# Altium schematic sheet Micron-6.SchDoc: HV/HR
size A4; Date: 21.04.2016; Author: Andrey Bykanov; CompanyName: http://микрон.net; Engineer: Andrey Bykanov; Address1: HV/HR Вольтметр; Address2: (с) ООО "Микрон Сервис"; Address3: Тула, 2012-16г.; Address4: adm@микрон.net; Revision: 2.02; PageSetup: Record=PageOptions¦CenterHorizontal=False¦CenterVertical=False¦PrintScale=0.98¦XCorrection=1.00¦YCorrection=1.00¦PrintKind=1¦BorderSize=5000000¦LeftOffset=0¦BottomOffset=0¦Orientation=2¦PaperLength=1000¦PaperWidth=1000¦Scale=100¦PaperSource=7¦PrintQuality=-3¦MediaType=1¦DitherType=10¦PrintScaleMode=0¦PaperKind=A4¦PaperIndex=9
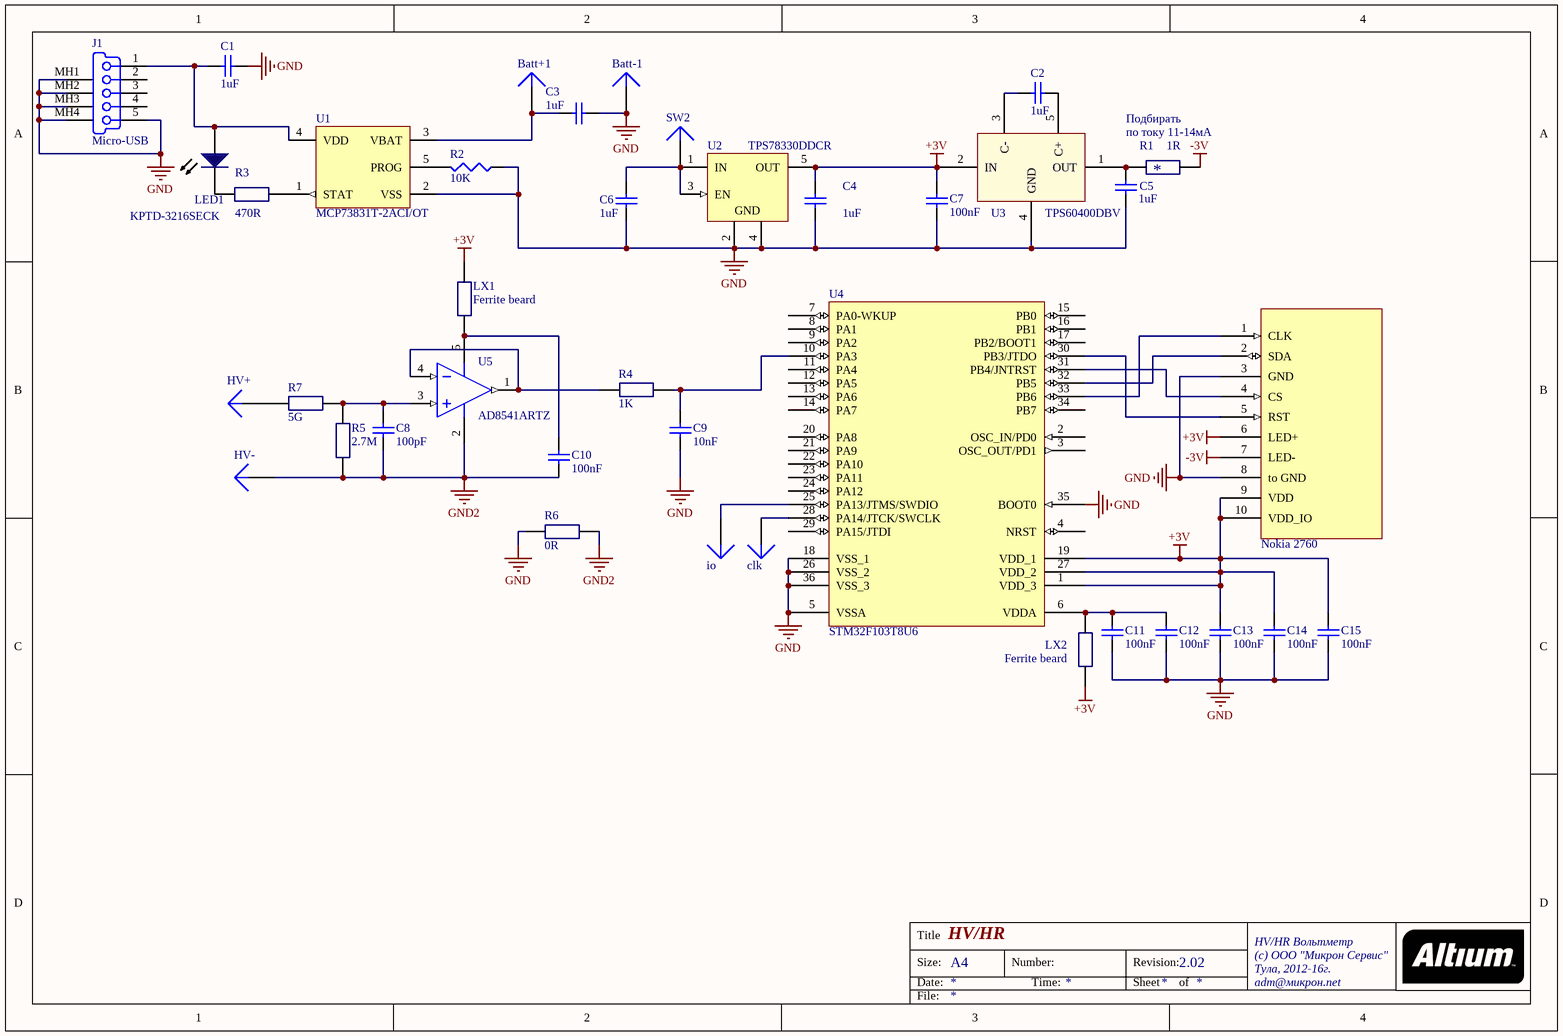
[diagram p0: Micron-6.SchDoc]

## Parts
Batt+1  (no value)  [Sensor contact]
Batt-1  (no value)  [Sensor contact]
C1  1uF  [0402 AVX]
C2  1uF  [0402 AVX]
C3  1uF  [0402 AVX]
C4  1uF  [1608[0603]]
C5  1uF  [0402 AVX]
C6  1uF  [1608[0603]]
C7  100nF  [0402 AVX]
C8  100pF  [0402 AVX]
C9  10nF  [0402 AVX]
C10  100nF  [0402 AVX]
C11  100nF  [0402 AVX]
C12  100nF  [0402 AVX]
C13  100nF  [0402 AVX]
C14  100nF  [0402 AVX]
C15  100nF  [0402 AVX]
clk  (no value)  [Sensor contact]
Display1  Nokia 2760  [DF23C-10DS-0.5V]
HV+  (no value)  [Sensor contact]
HV-  (no value)  [Sensor contact]
io  (no value)  [Sensor contact]
J1  Micro-USB  [47346-0001]
LED1  KPTD-3216SECK  [KPTD-3216SECK]
LX1  Ferrite beard  [Resistor]
LX2  Ferrite beard  [Resistor]
R1  1R  [1608[0603]]
R2  10K  [J1-0603]
R3  470R  [1608[0603]]
R4  1K  [1608[0603]]
R5  2.7M  [1608[0603]]
R6  0R  [1608[0603]]
R7  5G  [HVF2512T5007FE]
SW2  (no value)  [Sensor contact]
U1  MCP73831T-2ACI/OT  [SOT-23-OT5_N]
U2  TPS78330DDCR  [TI-DDC5_N]
U3  TPS60400DBV  [SOT-23-OT5_M]
U4  STM32F103T8U6  [VFQN36_V]
U5  AD8541ARTZ  [ADI-RJ-5_N]

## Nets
+3V: C4.2 C7.2 C13.1 C14.1 C15.1 Display1.6(LED+) Display1.9(VDD) Display1.10(VDD_IO) LX1.1(A) LX2.2 U2.5(OUT) U3.2(IN) U4.1(VDD_3) U4.19(VDD_1) U4.27(VDD_2)
-3V: Display1.7(LED-) R1.1(A)
GND: Batt-1.1 C1.1 C3.1 C4.1 C5.1 C6.1 C7.1 C9.2 C11.2 C12.2 C13.2 C14.2 C15.2 Display1.3(GND) Display1.8(to_GND) J1.5(GND) J1.MH1(Tab) J1.MH2(Tab) J1.MH3(Tab) J1.MH4(Tab) R2.1 R6.2 U1.2(VSS) U2.2(GND) U2.4(GND) U3.4(GND) U4.5(VSSA) U4.18(VSS_1) U4.26(VSS_2) U4.35(BOOT0) U4.36(VSS_3)
GND2: C8.2 C10.2 HV-.1 R5.2 R6.1(A) U5.2(-V)
NetBatt+1_1: Batt+1.1 C3.2 U1.3(VBAT)
NetC1_2: C1.2 J1.1(V_BUS_(5V)) LED1.2 U1.4(VDD)
NetC2_1: C2.1 U3.5(C+)
NetC2_2: C2.2 U3.3(C-)
NetC5_2: C5.2 R1.2 U3.1(OUT)
NetC6_2: C6.2 SW2.1 U2.1(IN) U2.3(EN)
NetC8_1: C8.1 R5.1(A) R7.2 U5.3(+IN_A)
NetC9_1: C9.1 R4.1(A) U4.10(PA3)
NetC10_1: C10.1 LX1.2 U5.5(+V)
NetC11_1: C11.1 C12.1 LX2.1(A) U4.6(VDDA)
Netclk_1: clk.1 U4.28(PA14/JTCK/SWCLK)
NetDisplay1_1: Display1.1(CLK) U4.33(PB6)
NetDisplay1_2: Display1.2(SDA) U4.32(PB5)
NetDisplay1_4: Display1.4(CS) U4.31(PB4/JNTRST)
NetDisplay1_5: Display1.5(RST) U4.30(PB3/JTDO)
NetHV+_1: HV+.1 R7.1(A)
Netio_1: io.1 U4.25(PA13/JTMS/SWDIO)
NetLED1_1: LED1.1 R3.2
NetR2_2: R2.2 U1.5(PROG)
NetR3_1: R3.1(A) U1.1(STAT)
NetR4_2: R4.2 U5.1(OUT_A) U5.4(-IN_A)

Not connected (* = marked no-connect by the designer): J1 2(D-) 3(D+) 4(NC); U4 2(OSC_IN/PD0) 3(OSC_OUT/PD1) 4(NRST) 7(PA0-WKUP) 8(PA1) 9(PA2) 11(PA4) 12(PA5) 13(PA6) 14(PA7) 15(PB0) 16(PB1) 17(PB2/BOOT1) 20(PA8) 21(PA9) 22(PA10) 23(PA11) 24(PA12) 29(PA15/JTDI) 34(PB7)

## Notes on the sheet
- Подбирать
- по току 11-14мА
- (near R1) *

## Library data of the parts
Batt+1 = Plug: Order: EEMB LP401230
Batt-1 clk HV+ HV- io SW2 = Plug
C1 C2 C5 = Cap Semi: Capacitor (Semiconductor SIM Model); Order: CC0402KRX5R5BB105; Avail: 1
C3 = Cap Semi: Capacitor (Semiconductor SIM Model); Order: CC0402KRX5R5BB105
C4 = CAPACITOR: Capacitor (Semiconductor SIM Model); Order: CC0603KRX5R7BB105
C6 = CAPACITOR: Capacitor (Semiconductor SIM Model); Order: CC0603KRX5R7BB105; Avail: 1
C7 C10-C15 = Cap Semi: Capacitor (Semiconductor SIM Model); Order: 0402ZD104KAT2A
C8 = Cap Semi: Capacitor (Semiconductor SIM Model); Order: GRM1555C1H101JD01D
C9 = Cap Semi: Capacitor (Semiconductor SIM Model); Order: CC0402KRX7R7BB103
Display1 = Nokia 2760: Order: Nokia 2760 ext + Socket Hirose DF23C-10DS-0.5V
J1 = 0481900001: USB On-The-Go (OTG) Mini-B Receptacle, Right Angle, SMT, 0.80mm (.031") Pitch, Solder Tabs with Back Cover, Recessed Type; Order: Molex 47346-0001
LED1 = KPTD-3216SECK: Avail: 1
LX1 LX2 = Resistor 0805: Order: BLM18HG102SN1D
R1 = Resistor 0805: Order: RC0603FR-071RL; Avail: 20
R2 = Res3: Resistor; Order: RC0603FR-1010KL; Avail: 1
R3 = Resistor 0805: Order: RC0603JR-07470RL; Avail: 1
R4 = Resistor 0805: Order: RC0603FR-101KL
R5 = Resistor 0805: Order: CRCW06032M70FKEA
R6 = Resistor 0805: Order: RC0603JR-100RL
R7 = Resistor 0805
U1 = MCP73831T-2ACI/OT: Miniature Single-Cell, Fully Integrated Li-Ion, Li-Polymer Charge Management Controller, 4.2V, 5-Pin SOT-23, Industrial Temperature, Tape and Reel; Avail: 1
U2 = TPS78330DDCR: Single Output LDO, 150 mA, Fixed 3 V Output, 2.2 to 5.5 V Input, with Ultra-Low IQ, 5-pin SOT (DDC), -40 to 105 degC, Green (RoHS & no Sb/Br); Manufacturer: Texas Instruments; Accuracy(%): 3; Iout(Max)(A): 0.15; Iq(Typ)(mA): 0.0005; Rating: Catalog; SubFamily: Single Channel LDO; Vdo(Typ)(mV): 130; Vin(Max)(V): 5.5; Vin(Min)(V): 2.2
U3 = TPS60400
U4 = STM32F103T8U6: STM32 ARM-based 32-bit MCU with 64 Kbytes Flash, 36-pin VFQFPN, Industrial Temperature
U5 = AD8541ARTZ-R2: Single Channel RRIO Operational Amplifier, 1 MHz BW, 920 mV/us SR, Industrial, 5-pin SOT23 (RJ-5), Reel; Generic Part Number: AD8541; Manufacturer: Analog Devices; Amplifiers Per Package: 1; Input Bias Current: 4pA; Input Offset Voltage: 1mV; Iq/Amp: 65uA; Small Signal Bandwidth: 1MHz; V Span Max: 5.5V; V Span Min: 2.7V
